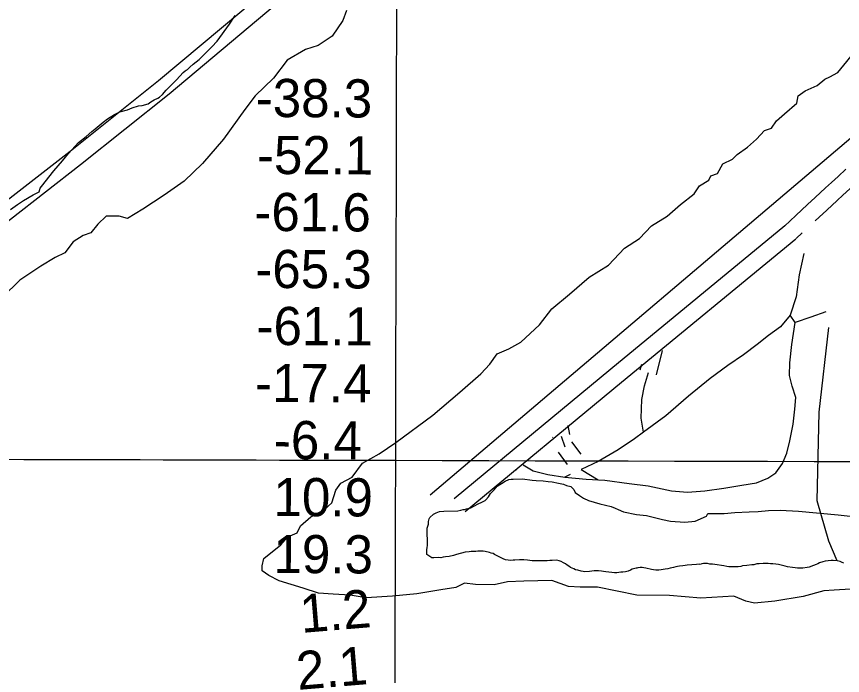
# Model space of a CAD drawing. Extents: x 3180038 to 3217926, y 922069 to 947485.
# Drawn here: x 3186224 to 3187673, y 933197 to 934354 of the extents above; entities that cross this region are included whole.
import ezdxf

# ---------------------------------------------------------------- set-up
doc = ezdxf.new("R2010")
doc.units = 0
for name, color, linetype in [('V-GRID-MAJR', 7, 'Continuous'), ('V-RIVR-EDGE', 7, 'Continuous'), ('V-RIVR-RANG', 7, 'Continuous'), ('V-ROAD-CNTR', 7, 'Continuous'), ('V-SITE-VEGE', 7, 'Continuous'), ('V-TOPO-SHOR', 7, 'Continuous')]:
    doc.layers.add(name, color=color, linetype=linetype)

msp = doc.modelspace()

# ---------------------------------------------------------------- linework, layer by layer
at = {"layer": 'V-GRID-MAJR'}
for points in [[(3186873.7, 927512.8), (3186889.6, 933574.8), (3186905.4, 939637.9), (3186921.3, 945701), (3186921.3, 945702.1)], [(3184280, 933581.8), (3186889.6, 933574.8), (3192108.7, 933561.5), (3197327.7, 933549), (3202546.8, 933537.2), (3207765.9, 933526.2), (3212985, 933516), (3215594.6, 933511.2)]]:
    msp.add_spline(points, degree=3, dxfattribs=at)
at = {"layer": 'V-RIVR-EDGE'}
for points in [[(3186803.4, 934364.2), (3186796.7, 934346.5), (3186777.9, 934319.1), (3186753.5, 934302.6), (3186731.2, 934295.4), (3186699, 934276.8), (3186675, 934245.2), (3186642.8, 934214.2), (3186625.1, 934190.3), (3186587.7, 934138.6), (3186550.7, 934095.6), (3186518.5, 934064.6), (3186483.7, 934039.8), (3186446.3, 934015.5), (3186419.3, 933999), (3186404.8, 934003.1), (3186381.9, 934003.2), (3186366.9, 933989.2), (3186354.9, 933974.2), (3186341.4, 933969.1), (3186323.7, 933958.2), (3186309.2, 933938.6), (3186292, 933930.8), (3186267.1, 933915.3), (3186230.2, 933891), (3186200.1, 933861)], [(3187687.5, 933348.8), (3187658.5, 933346.8), (3187640.3, 933345.8), (3187604.5, 933335.6), (3187554.7, 933327.4), (3187518.9, 933324.4), (3187503.9, 933327.5), (3187482.6, 933336.4), (3187425.1, 933332.9), (3187369.6, 933337.7), (3187312.5, 933338.4), (3187243.6, 933352.5), (3187213, 933352.1), (3187192.8, 933353.2), (3187163.7, 933364.1), (3187114.5, 933362.7), (3187085.9, 933361.7), (3187062.1, 933356.6), (3187029.4, 933356.7), (3187010.2, 933359.3), (3186995.2, 933351.6), (3186968.7, 933347.5), (3186926.7, 933340.4), (3186884.1, 933336.3), (3186837.5, 933333.8), (3186810, 933338), (3186779.9, 933340.2), (3186754, 933341.8), (3186727, 933350.2), (3186685.1, 933363.2), (3186666.9, 933372.6), (3186655.5, 933381), (3186655.6, 933389.8), (3186658.2, 933402.7), (3186688.3, 933426.5), (3186700.3, 933440.5), (3186716.9, 933447.7), (3186722.6, 933459.6), (3186740.8, 933475.7), (3186764.7, 933488.6), (3186777.7, 933500.5), (3186784.5, 933522.2), (3186793.4, 933534.6), (3186813.1, 933545), (3186831.3, 933569.8), (3186860.4, 933586.3), (3186890, 933606), (3186954.9, 933654), (3187002.2, 933694.4), (3187039.1, 933726.4), (3187054.7, 933743.5), (3187067.7, 933761.6), (3187088, 933770.4), (3187109.3, 933782.3), (3187142, 933812.8), (3187163.4, 933840.8), (3187194.6, 933866.6), (3187228.9, 933896.1), (3187262.6, 933917.3), (3187290.7, 933947.3), (3187317.2, 933964.3), (3187338.5, 933986.1), (3187365.5, 934003.1), (3187389.4, 934023.8), (3187413.3, 934042.4), (3187422.7, 934056.4), (3187438.8, 934066.2), (3187442.4, 934074), (3187453.9, 934078.1), (3187463.2, 934095.2), (3187480.4, 934103.4), (3187488.7, 934111.7), (3187506.9, 934124.1), (3187522.5, 934138.1), (3187536.5, 934153.6), (3187549, 934157.7), (3187557.3, 934170.7), (3187571.3, 934182.6), (3187593.2, 934201.7), (3187595.8, 934214.1), (3187607.7, 934223.4), (3187629, 934232.7), (3187642.5, 934243.6), (3187651.4, 934247.7), (3187665.4, 934255.4), (3187699.2, 934296.9)]]:
    msp.add_lwpolyline(points, dxfattribs=at)
at = {"layer": 'V-ROAD-CNTR'}
for p, q in [((3187605.3, 933937.9), (3187597.5, 933900.5)), ((3187597.5, 933900.5), (3187592.2, 933861.9)), ((3187592.2, 933861.9), (3187581.7, 933829.8)), ((3187643.9, 933835.2), (3187617.9, 933825.9)), ((3187581.7, 933829.8), (3187564.5, 933809.2)), ((3187590.3, 933816.8), (3187581.7, 933829.8)), ((3187617.9, 933825.9), (3187590.3, 933816.8)), ((3187564.5, 933809.2), (3187543.3, 933793.6)), ((3187584.6, 933778.2), (3187590.3, 933816.8)), ((3187543.3, 933793.6), (3187523.8, 933778.1)), ((3187523.8, 933778.1), (3187499.6, 933759.7)), ((3187580.7, 933745.9), (3187584.6, 933778.2)), ((3187347.2, 933725), (3187357.4, 933767.3)), ((3187499.6, 933759.7), (3187472.3, 933741)), ((3187318.4, 933733.4), (3187321.3, 933743.5)), ((3187472.3, 933741), (3187441.3, 933718.5)), ((3187580.2, 933723.4), (3187580.7, 933745.9)), ((3187326.3, 933705.6), (3187332.8, 933729.2)), ((3187441.3, 933718.5), (3187403.4, 933687.1)), ((3187585.1, 933704.8), (3187580.2, 933723.4)), ((3187321.5, 933681.6), (3187326.3, 933705.6)), ((3187591.3, 933684.9), (3187585.1, 933704.8)), ((3187320.3, 933648.6), (3187321.5, 933681.6)), ((3187403.4, 933687.1), (3187363.6, 933653)), ((3187590, 933664.6), (3187591.3, 933684.9)), ((3187587, 933638.3), (3187590, 933664.6)), ((3187324.4, 933624.1), (3187320.3, 933648.6)), ((3187363.6, 933653), (3187324.4, 933624.1)), ((3187191.7, 933635.7), (3187194.6, 933619.9)), ((3187581.2, 933609.3), (3187587, 933638.3)), ((3187179.8, 933617.3), (3187186.2, 933598.2)), ((3187324.4, 933624.1), (3187308.2, 933612.6)), ((3187164.9, 933615.7), (3187165.1, 933614.6)), ((3187198.1, 933607.3), (3187214.4, 933585.9)), ((3187308.2, 933612.6), (3187279.9, 933593.3)), ((3187575.6, 933587.5), (3187581.2, 933609.3)), ((3187174.3, 933589.1), (3187190.6, 933567.7)), ((3187279.9, 933593.3), (3187244.5, 933573)), ((3187568.2, 933569.1), (3187575.6, 933587.5)), ((3187125, 933576.2), (3187124, 933577.5)), ((3187113.2, 933567), (3187130.6, 933556.4)), ((3187244.5, 933573), (3187215.2, 933558.8)), ((3187215.2, 933558.8), (3187244.9, 933540.3)), ((3187556.1, 933552.7), (3187568.2, 933569.1)), ((3187101.3, 933557.7), (3187100.9, 933558.3)), ((3187130.6, 933556.4), (3187156.2, 933549.8)), ((3187156.2, 933549.8), (3187186.2, 933545.2)), ((3187195.7, 933549.9), (3187186.2, 933545.2)), ((3187186.2, 933545.2), (3187223.9, 933541.9)), ((3187542.3, 933543.5), (3187556.1, 933552.7)), ((3187223.9, 933541.9), (3187256.6, 933540)), ((3187256.6, 933540), (3187298.9, 933534.4)), ((3187298.9, 933534.4), (3187332.6, 933529.8)), ((3187332.6, 933529.8), (3187373.5, 933521.4)), ((3187464.9, 933526.2), (3187497, 933531.2)), ((3187497, 933531.2), (3187522.7, 933535.4)), ((3187522.7, 933535.4), (3187542.3, 933543.5)), ((3187373.5, 933521.4), (3187401.4, 933519)), ((3187401.4, 933519), (3187431.8, 933521.1)), ((3187431.8, 933521.1), (3187464.9, 933526.2))]:
    msp.add_line(p, q, dxfattribs=at)
for points in [[(3187236.4, 934925.7), (3187216.2, 934904.7), (3187182, 934869), (3186944.3, 934662), (3186835.5, 934547.5), (3186658.9, 934396.3), (3186473.5, 934240.5), (3186318.3, 934116.7), (3186133.8, 933973.2), (3185979.4, 933856.5), (3185785.7, 933729.6), (3185629, 933633), (3185541.8, 933597.7)], [(3187259, 934905.9), (3187237.8, 934883.9), (3187202.7, 934847.3), (3186965.1, 934640.3), (3186856.2, 934525.7), (3186678.3, 934373.4), (3186492.5, 934217.3), (3186336.8, 934093.1), (3186152.1, 933949.4), (3185996.6, 933832), (3185801.8, 933704.3), (3185642.6, 933606.1), (3185553, 933569.9)], [(3187679.4, 934085.5), (3187665.8, 934073.1), (3187654, 934062.3), (3187643.6, 934052.7), (3187625.5, 934036), (3187612, 934023.5), (3187591.7, 934004.6), (3187571.5, 933985.7)], [(3187729.5, 934090.3), (3187723.4, 934084.8), (3187715.1, 934077.3), (3187699.6, 934063.3), (3187686.1, 934051), (3187674.2, 934040.1), (3187663.9, 934030.7), (3187645.9, 934014), (3187632.4, 934001.5), (3187625.5, 933995)], [(3187572.2, 933986.3), (3187266.8, 933734.6), (3186992.2, 933507.4)], [(3187602.7, 933973.8), (3187592, 933963.8)], [(3187591.3, 933963.1), (3187285.9, 933711.4), (3187011.3, 933484.3)]]:
    msp.add_lwpolyline(points, dxfattribs=at)
at = {"layer": 'V-SITE-VEGE'}
for p, q in [((3186597.8, 934339.9), (3186607.8, 934355.4)), ((3186576.3, 934310.5), (3186597.8, 934339.9)), ((3186552.5, 934285.5), (3186566.9, 934300.2)), ((3186566.9, 934300.2), (3186576.3, 934310.5)), ((3186544.6, 934278.1), (3186552.5, 934285.5)), ((3186528.7, 934264.8), (3186534.5, 934269.9)), ((3186534.5, 934269.9), (3186544.6, 934278.1)), ((3186505, 934242.6), (3186516.5, 934255.1)), ((3186516.5, 934255.1), (3186520.1, 934258.1)), ((3186520.1, 934258.1), (3186522.3, 934259.6)), ((3186522.3, 934259.6), (3186524.4, 934260.3)), ((3186524.4, 934260.3), (3186528.7, 934264.8)), ((3186487, 934224.2), (3186505, 934242.6)), ((3186472.6, 934210.1), (3186475.5, 934212.3)), ((3186475.5, 934212.3), (3186480.5, 934216.8)), ((3186480.5, 934216.8), (3186487, 934224.2)), ((3186427.6, 934193.5), (3186438.5, 934196.6)), ((3186438.5, 934196.6), (3186445.1, 934197.4)), ((3186445.1, 934197.4), (3186455.2, 934200.4)), ((3186455.2, 934200.4), (3186460.3, 934204.1)), ((3186460.3, 934204.1), (3186466.1, 934207.1)), ((3186466.1, 934207.1), (3186472.6, 934210.1)), ((3186396.4, 934181.5), (3186405.8, 934186)), ((3186405.8, 934186), (3186418.9, 934189.8)), ((3186418.9, 934189.8), (3186427.6, 934193.5)), ((3186362.5, 934156.3), (3186376.2, 934168.1)), ((3186376.2, 934168.1), (3186384.1, 934174)), ((3186384.1, 934174), (3186396.4, 934181.5)), ((3186356.7, 934151.8), (3186362.5, 934156.3)), ((3186332.9, 934132.6), (3186346.6, 934143)), ((3186346.6, 934143), (3186356.7, 934151.8)), ((3186315.6, 934113.4), (3186332.9, 934132.6)), ((3186304.9, 934100.2), (3186315.6, 934113.4)), ((3186289.8, 934082.5), (3186304.9, 934100.2)), ((3186281.2, 934071.5), (3186289.8, 934082.5)), ((3186270.4, 934058.2), (3186281.2, 934071.5)), ((3186264, 934045.7), (3186266.1, 934052.3)), ((3186266.1, 934052.3), (3186270.4, 934058.2)), ((3186236.5, 934030.8), (3186253.9, 934040.5)), ((3186253.9, 934040.5), (3186264, 934045.7)), ((3186214.1, 934015.2), (3186226.4, 934023.4)), ((3186226.4, 934023.4), (3186236.5, 934030.8))]:
    msp.add_line(p, q, dxfattribs=at)
for points in [[(3187018.5, 933414.5), (3187011.7, 933413.5), (3186996.3, 933409.7), (3186990.9, 933407.8), (3186983.4, 933406.1), (3186976.9, 933405.2), (3186972.6, 933404.6), (3186968.7, 933403.9), (3186963.9, 933404.3), (3186956.5, 933403.8), (3186953, 933403.9), (3186944.1, 933409.6), (3186944.1, 933416.9), (3186944.7, 933422.7), (3186945.4, 933424.9), (3186945, 933455.5), (3186947.1, 933462.8), (3186947.1, 933467.2), (3186948.5, 933472.3), (3186949.2, 933474.5), (3186955.7, 933480.4), (3186960.7, 933482.7), (3186966.5, 933484.9), (3186973.8, 933485.8), (3186998.6, 933486.1), (3187003.7, 933487.6), (3187008, 933488.4), (3187010.2, 933488.4), (3187013.8, 933489.9), (3187021.1, 933491.4), (3187034.1, 933498.2), (3187040.7, 933501.2), (3187046.5, 933504.2), (3187047.9, 933505.6), (3187052.2, 933510.8), (3187055.8, 933516.7), (3187062.3, 933523.3), (3187067.3, 933529.2), (3187075.2, 933534.4), (3187081.7, 933538.1), (3187088.3, 933541.1), (3187091.9, 933541.9), (3187095.5, 933541.9), (3187112.3, 933542.1), (3187129.1, 933540.2), (3187135.7, 933539.5), (3187148, 933538.9), (3187156.8, 933537.6), (3187164.1, 933537), (3187175.1, 933534.9), (3187183.8, 933532.8), (3187189, 933530.7), (3187197, 933528.6), (3187202.2, 933523.6), (3187204.4, 933518.5), (3187211.8, 933512.8), (3187219.1, 933508.5), (3187227.9, 933504.2), (3187247.7, 933498.6), (3187267.4, 933493.8), (3187274.7, 933491), (3187279.8, 933488.8), (3187289.4, 933484.6), (3187312, 933479.8), (3187329.5, 933477.8), (3187357.3, 933470.9), (3187371.9, 933468.1), (3187396.7, 933466.2), (3187414.9, 933467.9), (3187434.5, 933476.9), (3187437.4, 933481.3), (3187465.8, 933481.7), (3187484.7, 933483.4), (3187509.5, 933484.4), (3187525.5, 933485.3), (3187543.7, 933487), (3187564.1, 933487.3), (3187596.2, 933485.5), (3187665.5, 933479.1), (3187713.6, 933473.8)], [(3187517.8, 933391.7), (3187516.7, 933391.2), (3187514.2, 933391.2), (3187505.8, 933390.1), (3187498.1, 933389.4), (3187494.9, 933388.4), (3187490.4, 933388.1), (3187479.7, 933388), (3187474, 933388.2), (3187470.2, 933388.6), (3187465.2, 933389.9), (3187449.2, 933392.2), (3187445.4, 933392.6), (3187440.8, 933392.7), (3187436.5, 933393.6), (3187429.7, 933394), (3187426.8, 933393.3), (3187423.8, 933392.3), (3187422.7, 933392.5), (3187417.5, 933391.8), (3187400.7, 933390.7), (3187397.5, 933390.4), (3187393.4, 933389.9), (3187387.6, 933388.9), (3187383.7, 933388.4), (3187380.8, 933387.7), (3187376.9, 933386.5), (3187371, 933385.3), (3187366.7, 933384.6), (3187362.4, 933383.6), (3187359, 933383.1), (3187355.4, 933382.8), (3187351.3, 933382.3), (3187346.1, 933382), (3187342, 933382.9), (3187338.2, 933383.3), (3187328.6, 933385.7), (3187324.7, 933386.1), (3187321.8, 933386.7), (3187318.4, 933386.5), (3187314.5, 933386.4), (3187312.3, 933385.7), (3187311.4, 933385.7), (3187304.3, 933383.6), (3187301.2, 933382.2), (3187297.1, 933380.5), (3187292.4, 933379.3), (3187288.1, 933378.6), (3187284.4, 933378.3), (3187277.6, 933377.3), (3187273.6, 933377.3), (3187268.6, 933377.7), (3187258.1, 933379.1), (3187254, 933380), (3187250.4, 933380.4), (3187245.2, 933380.8), (3187237.9, 933380.7), (3187233.4, 933380.2), (3187229.3, 933379.5), (3187221.3, 933379.1), (3187218.2, 933379.5), (3187215, 933380.2), (3187208.8, 933381.9), (3187205.2, 933382.8), (3187201.8, 933384.3), (3187196.3, 933387), (3187193.5, 933389), (3187190.3, 933391), (3187187.6, 933393), (3187184.2, 933395.2), (3187180.1, 933397.2), (3187176.6, 933398.3), (3187172.3, 933399.4), (3187163.9, 933399.3), (3187159.8, 933398.8), (3187155.5, 933398.5), (3187133.5, 933398.2), (3187129.2, 933398.6), (3187121, 933399.9), (3187114.4, 933400), (3187111, 933400.2), (3187106.9, 933400.2), (3187098.6, 933399.6), (3187095.4, 933399.6), (3187091.8, 933399.3), (3187087, 933399.7), (3187082.2, 933400.3), (3187077.9, 933402.1), (3187071, 933405.2), (3187063, 933409.8), (3187060.3, 933411.2), (3187057.3, 933411.8), (3187053.9, 933413.1), (3187046.6, 933414.6), (3187042.8, 933415.3), (3187037.1, 933415.2), (3187033.5, 933415.4), (3187030.1, 933415.1), (3187024.8, 933415), (3187021.7, 933414.6), (3187018.5, 933414.5)], [(3187675.9, 933394.1), (3187672.9, 933395.8), (3187669.1, 933397.4), (3187664.1, 933398.2), (3187656.8, 933399), (3187653.2, 933399), (3187643, 933397.7), (3187639.1, 933396.8), (3187633.2, 933394.7), (3187630.1, 933393.3), (3187627.1, 933392.3), (3187622.2, 933390.5), (3187614.7, 933387.4), (3187611.6, 933386.7), (3187603.9, 933385.7), (3187599.1, 933385.4), (3187594.3, 933385.6), (3187590.2, 933386), (3187585.7, 933386.6), (3187576.8, 933388.1), (3187572.5, 933389.2), (3187565.7, 933391.1), (3187561.3, 933392.2), (3187556.1, 933392.8), (3187551.3, 933393.2), (3187546.8, 933393.4), (3187542.9, 933393.8), (3187538.6, 933394), (3187534.1, 933393.9), (3187527.1, 933393.1), (3187522.8, 933392.9), (3187517.8, 933391.7)]]:
    msp.add_lwpolyline(points, dxfattribs=at)
at = {"layer": 'V-TOPO-SHOR'}
for points in [[(3186950.1, 933514), (3187757.4, 934199.7), (3187943.2, 934351.7)], [(3187664.1, 933398.2), (3187649.4, 933432.9), (3187629.1, 933503.8), (3187632.5, 933659.2), (3187649.4, 933807.8)]]:
    msp.add_lwpolyline(points, dxfattribs=at)

# ---------------------------------------------------------------- texts
at = {"layer": 'V-RIVR-RANG'}
for s, rotation, p in [('-38.3', 359.7083, (3186644, 934177.3)), ('-52.1', 359.7083, (3186646.1, 934077.3)), ('-61.6', 359.7083, (3186641.6, 933977.3)), ('-65.3', 359.7083, (3186643.2, 933877.3)), ('-61.1', 359.7083, (3186645.3, 933777.3)), ('-17.4', 359.7083, (3186642.7, 933677.3)), ('-6.4', 359.7083, (3186675.7, 933577.1)), ('10.9', 359.7083, (3186675.1, 933477.1)), ('19.3', 359.7083, (3186675.1, 933377.1)), ('1.2', 4.7567, (3186724.4, 933271.9)), ('2.1', 4.7567, (3186718.1, 933171.9))]:
    msp.add_text(s, height=67, rotation=rotation, dxfattribs=at).set_placement(p)

doc.saveas('drawing.dxf')
